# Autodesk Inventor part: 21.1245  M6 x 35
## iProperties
Created: 2006-02
Part Number: 21.1245  M6 x 35
Material: Steel, Mild
Description: Cylinder Head Cap Screw
Document SubType Name: Modeling
Standard: DIN 7984
Designer: Andy Moles
Standards Organization: DIN
Language: en-US
Size Designation: M6 x 35
Categories: <MemberInstance><Categories><Category DisplayName="Fasteners" InternalName="e4da775c-781d-43d5-af7c-5136215cf5a6" Mnemonic="FSTN"><Category DisplayName="Bolts"
Density: 7.86 g/cm^3
Mass: 9.81936 g
Surface Area: 9.72304 cm^2
Volume: 1.24928 cm^3
Author: Andy Moles
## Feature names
1. Body [Revolution]
2. Slot [Extrusion]
3. Fillet1
4. Chamfer1
